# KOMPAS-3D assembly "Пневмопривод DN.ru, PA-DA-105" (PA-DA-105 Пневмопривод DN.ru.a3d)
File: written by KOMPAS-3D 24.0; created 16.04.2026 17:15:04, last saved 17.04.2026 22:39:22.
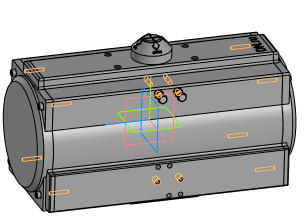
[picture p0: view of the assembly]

Document properties: Автор: DN.ru; Полное имя файла: C:\Работа\PA-DA-х Пневмопривод DN.ru\105\исходные материалы\PA-DA-105 Пневмопривод DN.ru.a3d

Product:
- Component [detail]: Пневмопривод DN.ru  | designation PA-DA-105  | qty 1  | pos. 1  | Масса: 6.8; Раздел спецификации: Прочие изделия; Примечание: D290-00296; Автор: DN.ru; source file: PA-DA-105 Пневмопривод DN.ru.m3d
- Component [standard]: Винт М4-6gx30 ГОСТ 11738-84  | qty 8  | Масса: 0.00361; Раздел спецификации: Стандартные изделия; Рассекать на разрезах: no
- Component [standard]: Болт М5-6gx50 ГОСТ 7805-70  | qty 2  | Масса: 0.008999; Раздел спецификации: Стандартные изделия; Рассекать на разрезах: no
- Component [standard]: Гайка М5-6H ГОСТ 5915-70  | qty 2  | Масса: 0.00144; Раздел спецификации: Стандартные изделия; Рассекать на разрезах: no
- Part/product: Пневмопривод DN.ru  | designation PA-DA-105
    Масса: 6.8
    Раздел спецификации: Прочие изделия
    Примечание: D290-00296

Expressions: D290-00293; D290-00296
Referenced files in C:\Работа\PA-DA-х Пневмопривод DN.ru\052\исходные материалы\: PA-DA-052 Пневмопривод DN.ru.m3d
Referenced files in C:\Работа\PA-DA-х Пневмопривод DN.ru\105\исходные материалы\: PA-DA-105 Пневмопривод DN.ru.m3d
Referenced files in C:\Program Files\ASCON\KOMPAS-3D v24\Libs\PolynomLib\DATA\vault\Methods\Kompas\3D\: PLib_Screw_GOST_11738_1500.m3d, PLib_Bolt_1_900.m3d, PLib_Nut_OST92_900.m3d
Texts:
  PA-DA-052
  Крепежное изделие ГОСТ
  BOSimple***PART:1ff84fa3-e62c-5a6d-126f-35e3f1af4542***SHORTLOC:Root±30±20±10±80±10±GMC90[Нет;Без покрытия;Без указания материала;0,7;-;30;4]
  BOSimple***PART:53acba15-081d-1c02-6810-072b309dd366***SHORTLOC:Root±30±20±10±80±10±©{}30±©{BASE}130±30[Нет;Без покрытия;Без указания материала;50;5;8;0,8;-]
  BOSimple***PART:0338bb82-6b79-df62-da33-8b23172f1b3e***SHORTLOC:Root±30±10±20±©{}110±10±50±60[Нет;Без покрытия;Без указания материала;-;5;0,8;8]
  Программные изделия  и базы данных
  PA-DA-105
  PA-DA-105 Пневмопривод DN.ru
  Винт М4-6gx30 ГОСТ 11738-84 (1)
  Винт М4-6gx30 ГОСТ 11738-84 (2)
  Винт М4-6gx30 ГОСТ 11738-84 (3)
  Винт М4-6gx30 ГОСТ 11738-84 (4)
  Винт М4-6gx30 ГОСТ 11738-84 (5)
  Винт М4-6gx30 ГОСТ 11738-84 (6)
  Винт М4-6gx30 ГОСТ 11738-84 (7)
  Винт М4-6gx30 ГОСТ 11738-84 (8)
  Болт М5-6gx50 ГОСТ 7805-70 (1)
  hole1
  hole2
  Болт М5-6gx50 ГОСТ 7805-70 (2)
  Гайка М5-6H ГОСТ 5915-70 (1)
  bcut1
  hcut1
  cut1
  Гайка М5-6H ГОСТ 5915-70 (2)
  Plane. Начало координат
